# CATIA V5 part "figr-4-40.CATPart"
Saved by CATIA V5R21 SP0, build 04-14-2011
Part number: Part1
Bounding box of the stored display mesh (mm): x -59.931 to 60.019, y -73.049 to 76.86, z -59.931 to 60.019
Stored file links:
  D:\CATIA V5R21 E-RESOURCES\CATIA-V5R21\catia-v5r21-prt\c04-catia-v5r20-prt\catia-v5r21-figr-4-40.CATPart
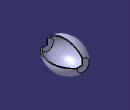
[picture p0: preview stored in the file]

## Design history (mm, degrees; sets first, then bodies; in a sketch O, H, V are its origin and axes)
Body1 (main body)
  Sketch1 on yz-plane, origin (0, 0, 0), H (0, 1, 0), V (0, 0, 1)
    point P1 (76.8601, 0)
    line L1 (76.8601, 0) -> (76.8601, 25)
    construction line L2 through (0, 0) direction (-1, 0)
    point P5 (-73.049, 0)
    line L3 (-73.049, 0) -> (-73.049, 25)
    axis line L4 (-100, 0) -> (100, 0)
    arc A1 centre (1.9056, -37.7079) radius 97.7265 from (76.8601, 25) to (-73.049, 25) ccw
    point P10 (0, 60)
    length L1 = 25
    length L3 = 25
    horizontal: L4 H
    vertical: L3 V, L1 V
    coincidence: P1 L4, L4 L2, P5 L4, L4 H, A1 P10, P10 V
  Shaft1: profile Sketch1, axis Sketch1.L4, angle 270, thin wall 4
